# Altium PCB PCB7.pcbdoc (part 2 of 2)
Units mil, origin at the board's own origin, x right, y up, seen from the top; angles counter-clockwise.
Board outline 2240.69 x 1522.77 mil, 8 copper layers (Top Layer, Inner1, Inner2, Inner3, Inner4, Inner5, Inner6, Bottom Layer); 54 components, 78 nets, 968 pads, 282 vias.
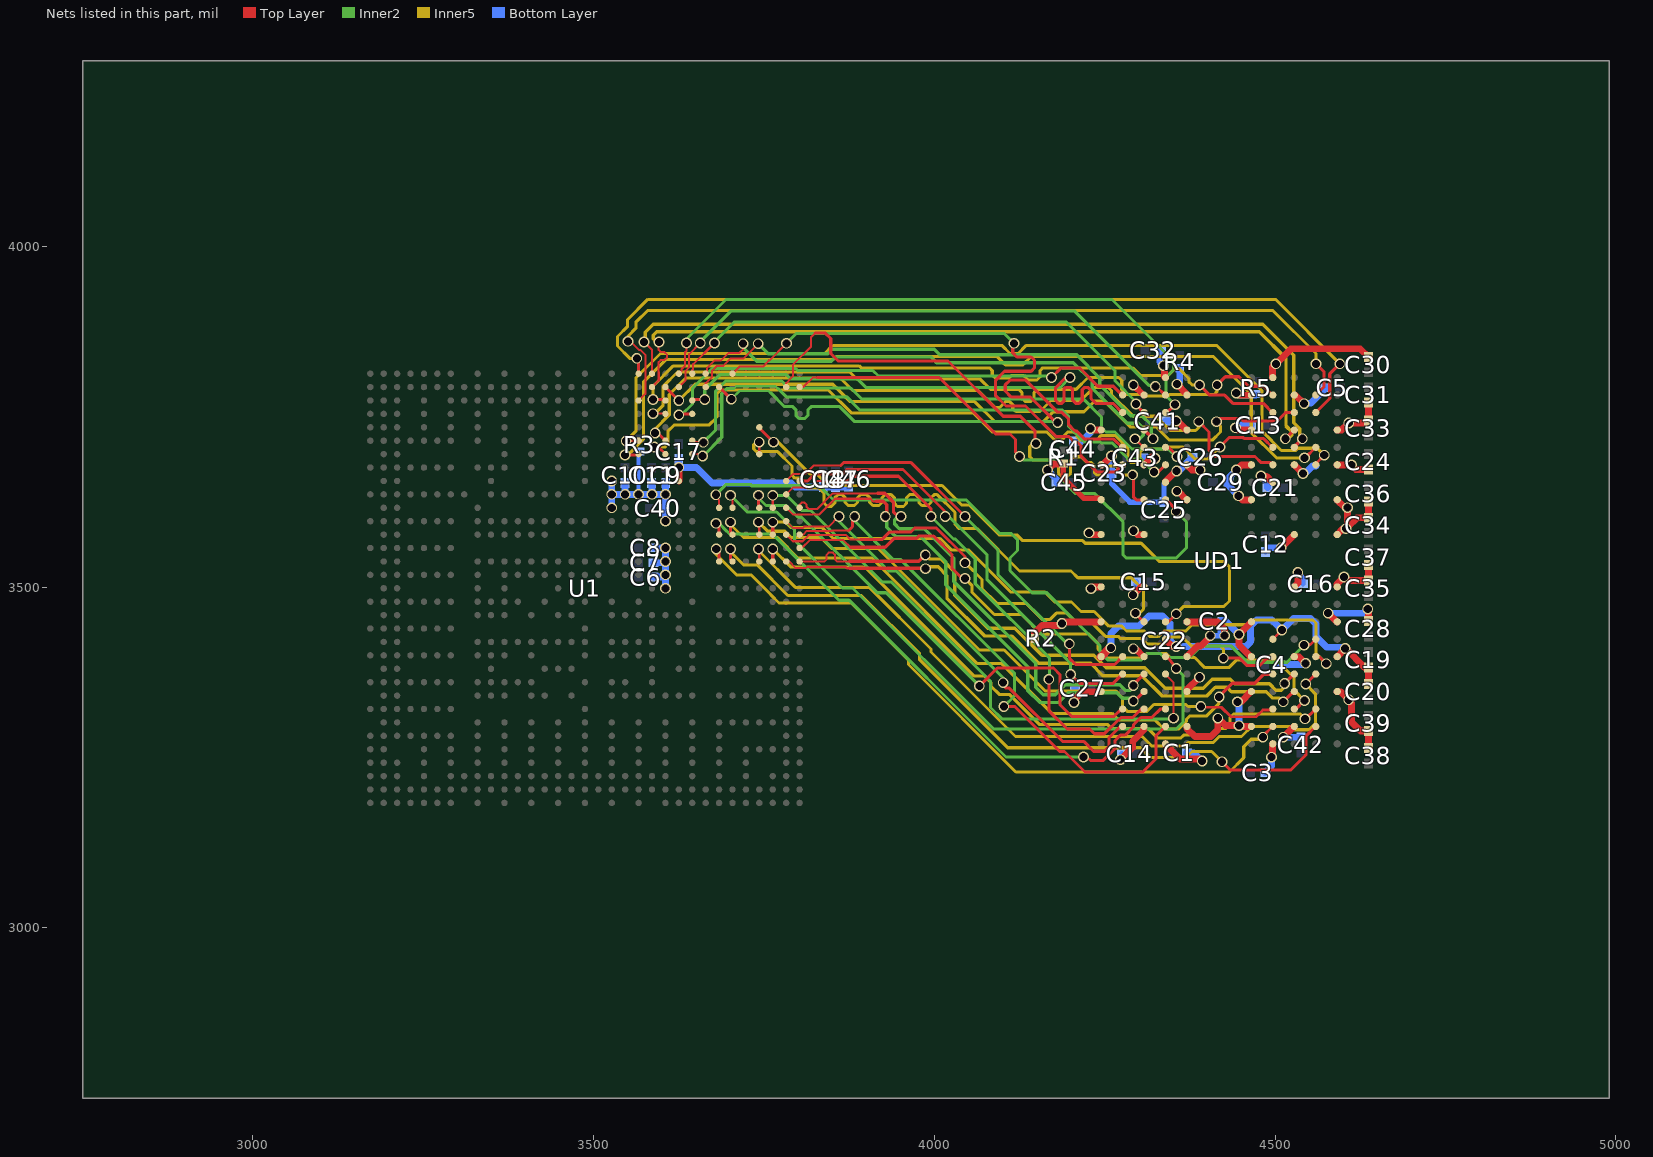
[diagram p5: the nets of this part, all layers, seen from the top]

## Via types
v1: diameter 15.75, hole 11.81, Top Layer to Bottom Layer, 282 vias

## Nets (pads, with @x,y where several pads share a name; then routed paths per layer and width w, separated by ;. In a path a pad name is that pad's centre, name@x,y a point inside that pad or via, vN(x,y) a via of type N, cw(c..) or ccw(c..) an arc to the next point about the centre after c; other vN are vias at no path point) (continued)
SCS0-A: U1.AN32 UD1.H4 | length 826.4
  Top Layer w3: U1.AN32@3802.23,3793.68 3807.9,3793.68 3821.99,3807.77 3827.87,3807.77
  Top Layer w4.5: 3827.87,3807.77 4007,3807.77 4090,3724.77 4111,3724.77 4119,3716.77 4119,3697.77 v1(4125,3691.77) ; UD1.H4@4338.78,3628.07 4340.7,3628.07 4355,3613.77 v1(4355,3610.77)
  Inner2 w4.5: v1(4125,3691.77) 4130,3686.77 4179.49,3686.77 4189.5,3676.76 4189.5,3654.76 4206.99,3637.27 4235.5,3637.27 4277,3595.77 4277,3547.27 4281.5,3542.77 4355,3542.77 4370,3557.77 4370,3595.77 v1(4355,3610.77)
SCS0-B: U1.AK29 UD1.R4 | length 932.3
  Top Layer w4.5: U1.AK29@3743.18,3734.62 3743.18,3733.59 v1(3764,3712.77) ; UD1.R4@4338.78,3448.93 4343.16,3448.93 v1(4355,3460.77)
  Inner5 w4.5: v1(3764,3712.77) 3771,3712.77 3818,3665.77 3828,3665.77 3844.5,3649.27 4011.43,3649.27 4039.93,3620.77 4051,3620.77 4095,3576.77 4121,3576.77 4129.5,3568.27 4217.54,3568.27 4221.43,3564.38 4303.39,3564.38 4330,3537.77 4425,3537.77 4433,3529.77 4433,3479.77 4425,3471.77 4366,3471.77 v1(4355,3460.77)
SCS1-A: U1.AM32 UD1.H3 | length 813.7
  Top Layer w3: U1.AM32@3782.55,3793.68 3782.56,3799.47 3792.38,3809.28 3792.38,3826.15 3819.31,3853.08 3819.31,3867.08 3825,3872.77
  Top Layer w4.5: 3825,3872.77 3840,3872.77 3848,3864.77 3848,3842.77 3859,3831.77 4020,3831.77 4101,3750.77 4126.02,3750.77 4148,3728.79 4148,3711.77 v1(4149,3710.77) ; v1(4291,3664.77) 4292,3663.77 4292,3632.57 4296.5,3628.07 UD1.H3@4307.28,3628.07
  Inner5 w4.5: v1(4149,3710.77) 4144.5,3710.77 4140,3706.27 4140,3691.27 4144.5,3686.77 4177.5,3686.77 4182,3682.27 4182,3667.27 4186.5,3662.77 4195.5,3662.77 4200,3667.27 4200,3686.83 4204.5,3691.33 4215.44,3691.33 4224,3682.77 4230.5,3682.77 4235,3678.27 4235,3667.77 4238,3664.77 4247.96,3664.77 4252.46,3669.27 4252.46,3673.27 4256.96,3677.77 4265.96,3677.77 4270.46,3673.27 4270.46,3669.27 4274.96,3664.77 v1(4291,3664.77)
SCS1-B: U1.AK27 UD1.R3 | length 888.4
  Top Layer w4: v1(3743,3712.77) 3743.18,3712.59 U1.AK27@3743.17,3695.18
  Top Layer w4.5: v1(4295,3461.77) 4295,3461.2 UD1.R3@4307.27,3448.93
  Inner5 w4.5: v1(3743,3712.77) 3738.62,3712.77 3734.99,3709.14 3734.99,3702.78 3739,3698.77 3770,3698.77 3791,3677.77 3791,3664.27 3795.25,3660.02 3803.75,3660.02 3808,3655.77 3808,3650.77 3813,3645.77 3830,3645.77 3838,3637.77 3838,3623.46 3842.81,3618.65 3849.18,3618.65 3854,3623.47 3854,3631.27 3858.5,3635.77 3864.66,3635.77 3869.16,3631.27 3869.16,3624.27 3873.66,3619.77 3882.66,3619.77 3887.16,3624.27 3887.16,3631.27 3891.66,3635.77 3900.66,3635.77 3905.16,3631.27 3905.16,3624.27 3909.66,3619.77 3918.66,3619.77 3923.16,3624.27 3923.16,3631.27 3927.66,3635.77 3936.66,3635.77 3941.16,3631.27 3941.16,3622.97 3945.67,3618.46 3954.65,3618.46 3959.16,3622.97 3959.16,3631.27 3963.66,3635.77 3972.66,3635.77 3977.16,3631.27 3977.16,3624.27 3981.66,3619.77 3990.66,3619.77 3995.16,3624.27 3995.16,3631.27 3999.66,3635.77 4004.16,3635.77 4030.25,3609.68 4030.25,3591.96 4036.45,3585.76 4062.86,3585.76 4124.85,3523.77 4200.51,3523.77 4210.51,3513.77 4289,3513.77 4307,3495.77 4307,3467.77 4301,3461.77 v1(4295,3461.77)
SDQ0: U1.AE28 UD1.E4 | length 860.7
  Top Layer w4.5: U1.AE28@3644.75,3714.94 3647.18,3712.51 v1(3660.95,3712.51) ; UD1.E4@4338.78,3704.84 4343.93,3704.84 4356,3692.77 v1(4356,3691.77)
  Inner2 w4.5: v1(3660.95,3712.51) 3679,3730.56 3679,3787.77 3693.44,3802.21 3776.56,3802.21 3786.5,3792.27 3877.16,3792.27 3893.16,3776.27 4218.5,3776.27 4245,3749.77 4245,3734.77 4252,3727.77 4265,3727.77 4290,3702.77 4343,3702.77 4354,3691.77 v1(4356,3691.77)
SDQ1: U1.AE27 UD1.F4 | length 840.3
  Top Layer w3: U1.AE27@3644.75,3695.25 3657.21,3695.25 v1(3659.96,3692.51)
  Top Layer w4.5: v1(4322.52,3668.82) 4323.05,3668.82 4324,3669.77 4329.3,3669.77 UD1.F4@4338.78,3679.25
  Inner2 w3: 3706,3791.77 3709,3794.77 3767,3794.77 3770,3791.77
  Inner2 w4.5: v1(3659.96,3692.51) 3660.74,3692.51 3688,3719.77 3688,3783.77 3696,3791.77 3706,3791.77 ; 3770,3791.77 3782.5,3779.27 3871.5,3779.27 3891,3759.77 4188,3759.77 4196.75,3751.02 4196.75,3736.01 4219.47,3713.29 4243.14,3713.29 4245.16,3711.27 4261.5,3711.27 4285,3687.77 4303.57,3687.77 v1(4322.52,3668.82)
SDQ2: U1.AG32 UD1.E2 | length 877.4
  Top Layer w4.5: U1.AG32@3684.12,3793.68 v1(3702,3775.77) ; v1(4181,3741.77) 4178,3741.77 4141,3778.77 4113,3778.77 4104,3787.77 4104,3796.77 4111,3803.77 4134,3803.77 4181,3756.77 4187,3756.77 4197,3746.77 4197,3738.36 4205.51,3729.85 4206.34,3729.85 4207.42,3728.77 4209,3728.77 4220.59,3717.18 4263.45,3717.18 UD1.E2@4275.79,3704.84
  Inner2 w3: v1(3702,3775.77) 3714,3787.77 3757,3787.77 3759,3785.77
  Inner2 w4.5: 3759,3785.77 3780,3764.77 3792.2,3764.77 3796.7,3760.27 3796.7,3752.27 3801.2,3747.77 3810.2,3747.77 3814.7,3752.27 3814.7,3760.27 3819.2,3764.77 3861,3764.77 3883,3742.77 4180,3742.77 v1(4181,3741.77)
SDQ3: U1.AH33 UD1.F2 | length 839.4
  Top Layer w3: U1.AH33@3703.81,3813.36 3714.22,3823.77 3749,3823.77 3752.5,3827.27 3752.5,3827.88 3756.89,3832.27 3757.5,3832.27 v1(3783,3857.77)
  Top Layer w4.5: v1(4117,3857.77) 4115,3855.77 4115,3843.77 4121,3837.77 4142,3837.77 4147,3832.77 4147,3821.77 4142,3816.77 4103,3816.77 4090,3803.77 4090,3780.77 4105,3765.77 4133.66,3765.77 4178.66,3720.77 4197.5,3720.77 4206,3712.27 4210.5,3712.27 4215,3707.77 4215,3692.77 4239.09,3668.68 4265.22,3668.68 UD1.F2@4275.79,3679.25
  Inner2 w4.5: v1(3783,3857.77) 3797.75,3872.52 4102.25,3872.52 v1(4117,3857.77)
SDQ4: U1.AE30 UD1.B2 | length 740.8
  Top Layer w4.5: v1(3625,3752.77) 3626.54,3754.31 U1.AE30@3644.75,3754.31 ; v1(4172,3807.52) 4186.25,3821.77 4213,3821.77 4240,3794.77 4262.63,3794.77 UD1.B2@4275.79,3781.61
  Inner2 w4.5: v1(3625,3752.77) 3629,3752.77 3645,3768.77 3645,3791.77 3674,3820.77 3797,3820.77 3800,3817.77 3910,3817.77 3918,3809.77 4169.75,3809.77 v1(4172,3807.52)
SDQ5: U1.AD32 UD1.B4 | length 831.9
  Top Layer w3: U1.AD32@3625.07,3793.68 3634.93,3803.54 3634.93,3817.43 3640.15,3822.65 3640.15,3841.9 v1(3656.48,3858.23)
  Top Layer w4.5: v1@4324.38,3794.39 4325,3793.77 4326.62,3793.77 UD1.B4@4338.78,3781.61
  Inner2 w4.5: v1(3656.48,3858.23) 3656.48,3860.23 3701.77,3905.52 4205.25,3905.52 4314.7,3796.07 4322.61,3796.07 v1(4324.29,3794.39)
SDQ6: U1.AE31 UD1.C2 | length 817.4
  Top Layer w4.5: U1.AE31@3644.75,3773.99 3646.24,3775.49 v1(3663.07,3775.49) ; v1(4199,3807.52) 4192.75,3807.52 4178,3792.77 4178,3773.77 4182,3769.77 4187,3769.77 4190,3772.77 4190,3790.12 4193,3793.12 4199.65,3793.12 4203,3789.77 4203,3774.27 4207.5,3769.77 4212.5,3769.77 4217,3774.27 4217,3789.77 4220,3792.77 4226,3792.77 4230,3788.77 4230,3776.52 4236.75,3769.77 4262.04,3769.77 UD1.C2@4275.79,3756.02
  Inner2 w4.5: v1(3663.07,3775.49) 3663.07,3789.84 3685,3811.77 3783,3811.77 3789,3805.77 3887,3805.77 3900,3792.77 4184.25,3792.77 v1(4199,3807.52)
SDQ7: U1.AD33 UD1.C4 | length 924.5
  Top Layer w3: U1.AD33@3625.07,3813.36 3628.93,3817.22 3628.93,3819.92 3634.15,3825.14 3634.15,3844.39 3636.38,3846.62 v1(3636.38,3858.33)
  Top Layer w4.5: UD1.C4@4338.78,3756.02 4341.25,3756.02 v1(4353,3767.77)
  Inner2 w4.5: v1(3636.38,3858.33) 3636.38,3864.15 3694.25,3922.02 4260.75,3922.02 4351,3831.77 4351,3818.77 4340,3807.77 4340,3780.77 v1(4353,3767.77)
SDQ8: U1.AC27 UD1.E9 | length 1109.3
  Top Layer w4.5: v1(3588.95,3705.51) 3595.12,3705.51 U1.AC27@3605.36,3695.18 ; v1(4419,3705.77) 4433,3719.77 4453,3719.77 4454.89,3717.88 4483.22,3717.88 UD1.E9@4496.26,3704.84
  Inner5 w4.5: v1(3588.95,3705.51) 3604.49,3705.51 3609,3710.02 3609,3728.77 3618,3737.77 3669,3737.77 3681,3749.77 3681,3783.77 3686.25,3789.02 3844.74,3789.02 3877.99,3755.77 4056.9,3755.77 4084.9,3727.77 4165,3727.77 4177,3715.77 4186.77,3715.77 4191.27,3720.27 4191.27,3723.27 4195.77,3727.77 4204.77,3727.77 4209.27,3723.27 4209.27,3720.27 4213.77,3715.77 4238,3715.77 4245,3722.77 4265,3722.77 4284,3703.77 4284,3687.27 4288.5,3682.77 4297.5,3682.77 4302,3687.27 4302,3698.27 4306.5,3702.77 4337,3702.77 4340,3705.77 4365,3705.77 4383,3687.77 4401,3687.77 v1(4419,3705.77)
SDQ9: U1.AC28 UD1.F9 | length 1107.7
  Top Layer w4.5: v1(3590.28,3726.13) 3594.19,3726.13 U1.AC28@3605.36,3714.86 ; v1(4388,3742.77) 4403,3727.77 4403,3700.77 4412,3691.77 4470.62,3691.77 4479.62,3682.77 4492.74,3682.77 UD1.F9@4496.26,3679.25
  Inner5 w4.5: v1(3590.28,3726.13) 3590.28,3732.05 3611,3752.77 3611,3782.77 3635,3806.77 3862,3806.77 3880,3788.77 4064,3788.77 4089.31,3763.46 4095.69,3763.46 4105,3772.77 4110,3772.77 4115,3767.77 4115,3762.27 4119.5,3757.77 4155,3757.77 4171.08,3773.85 4214.92,3773.85 4233.84,3792.77 4255.5,3792.77 4260,3788.27 4260,3782.77 4292,3750.77 4325,3750.77 4346,3729.77 4383.5,3729.77 4388,3734.27 v1(4388,3742.77)
SDQ10: U1.AC30 UD1.B9 | length 1059.2
  Top Layer w3: v1(3587.08,3754.49) 3605.2,3754.49 U1.AC30@3605.38,3754.31
  Top Layer w4.5: v1(4415,3796.77) 4427,3808.77 4447,3808.77 4461,3794.77 4483.1,3794.77 UD1.B9@4496.26,3781.61
  Inner5 w4.5: v1(3587.08,3754.49) 3589.72,3754.49 3602,3766.77 3602,3794.77 3623,3815.77 3876.01,3815.77 3886.51,3805.27 4067.5,3805.27 4082.42,3790.35 4123.9,3790.35 4128.4,3785.85 4128.4,3777.27 4132.9,3772.77 4141.9,3772.77 4146.4,3777.27 4146.4,3785.85 4150.9,3790.35 4208.08,3790.35 4225.5,3807.77 4270.5,3807.77 4275,3803.27 4275,3789.77 4282,3782.77 4306,3782.77 4308,3780.77 4343,3780.77 4345,3782.77 4410.5,3782.77 4415,3787.27 v1(4415,3796.77)
SDQ11: U1.AC31 UD1.C9 | length 1026.9
  Top Layer w4.5: v1(3587.07,3775.49) 3603.89,3775.49 U1.AC31@3605.38,3773.99 ; v1(4389,3796.77) 4404,3781.77 4426,3781.77 4438,3769.77 4482.51,3769.77 UD1.C9@4496.26,3756.02
  Inner5 w4.5: v1(3587.07,3775.49) 3587.07,3794.84 3617,3824.77 3889.63,3824.77 3892.63,3821.77 4081,3821.77 4085,3817.77 4085,3811.27 4089.5,3806.77 4110,3806.77 4114,3810.77 4131,3810.77 4137.92,3803.85 4150.5,3803.85 4155,3808.35 4155,3817.77 4159,3821.77 4291,3821.77 4302,3810.77 4343,3810.77 4352.81,3820.58 4359.19,3820.58 4373.5,3806.27 4373.5,3801.27 4378,3796.77 v1(4389,3796.77)
SDQ12: U1.AA33 UD1.C11 | length 1287.4
  Top Layer w4.5: v1(3563.34,3835.77) 3566.01,3833.1 U1.AA33@3566.01,3813.36 ; UD1.C11@4559.25,3756.02 4580.18,3776.95 4580.18,3812.95 v1(4595,3827.77)
  Inner5 w4.5: v1(3563.34,3835.77) 3553,3835.77 3535,3853.77 3535,3867.77 3550,3882.77 3550,3892.77 3579.5,3922.27 4500.5,3922.27 v1(4595,3827.77)
SDQ13: U1.AA31 UD1.B11 | length 1239.9
  Top Layer w3: v1(3550.53,3860.77) 3554.01,3860.77 3566.51,3848.27 3568.52,3848.27 3575.84,3840.95 3575.84,3783.82 U1.AA31@3566.01,3773.99
  Top Layer w4.5: UD1.B11@4559.25,3781.61 4572,3794.36 4572,3815.77 v1(4560,3827.77)
  Inner5 w4.5: v1(3550.53,3860.77) 3550.53,3868.29 3562,3879.76 3562,3888.77 3579,3905.77 4497,3905.77 4560,3842.77 v1(4560,3827.77)
SDQ14: U1.AA28 UD1.F11 | length 1280.3
  Top Layer w4: v1(3547.7,3714.49) 3548.15,3714.94 U1.AA28@3565.99,3714.86
  Top Layer w4.5: UD1.F11@4559.25,3679.25 4559.25,3680.76 v1(4572.14,3693.65)
  Inner5 w4.5: v1(3547.7,3714.49) 3562,3728.79 3562,3806.77 3598,3842.77 3839,3842.77 3851,3854.77 4099,3854.77 4111,3842.77 4123,3842.77 4135,3854.77 4414,3854.77 4481,3787.77 4481,3728.77 4509.19,3700.58 4530.81,3700.58 4534,3703.77 4561.91,3703.77 4572,3693.68 v1@4572.1,3693.68
SDQ15: U1.AA27 UD1.E11 | length 1253.4
  Top Layer w4.5: v1(3546,3693.77) 3564.53,3693.77 U1.AA27@3565.99,3695.18 ; v1(4543,3689.77) 4544.18,3689.77 UD1.E11@4559.25,3704.84
  Inner5 w4.5: v1(3546,3693.77) 3550,3693.77 3573,3716.77 3573,3800.77 3606,3833.77 3851,3833.77 3855.5,3838.27 4092.16,3838.27 4104.16,3826.27 4129.84,3826.27 4141.84,3838.27 4409.5,3838.27 4465,3782.77 4465,3726.77 4502,3689.77 v1(4543,3689.77)
SDQ16: U1.AM25 UD1.U2 | length 665.7
  Top Layer w3: U1.AM25@3782.55,3655.88 3792.38,3665.7 3810.14,3665.7 3822.71,3678.27 3862.31,3678.27
  Top Layer w4.5: 3862.31,3678.27 3866.81,3682.77 3966,3682.77 v1(4045,3603.77) ; v1(4198,3416.77) 4198,3395.77 4207.27,3386.5 4264.54,3386.5 UD1.U2@4275.79,3397.75
  Inner2 w4.5: v1(4045,3603.77) 4045,3603.11 4093.5,3554.61 4093.5,3518.27 4195,3416.77 v1(4198,3416.77)
SDQ17: U1.AN25 UD1.V2 | length 651.2
  Top Layer w4.5: U1.AN25@3802.23,3655.88 3814.11,3655.88 3824,3665.77 3864,3665.77 3871,3672.77 3954,3672.77 4015,3611.77 4015,3604.77 v1(4016,3603.77) ; v1(4200,3371.77) 4212.86,3358.91 4262.54,3358.91 UD1.V2@4275.79,3372.16
  Inner2 w4.5: v1(4016,3603.77) 4021,3603.77 4077,3547.77 4077,3511.43 4200,3388.43 v1(4200,3371.77)
SDQ18: U1.AH23 UD1.U4 | length 946.1
  Top Layer w3: v1(3700.96,3634.77) 3703.82,3631.91 U1.AH23@3703.82,3616.52
  Top Layer w4.5: UD1.U4@4338.78,3397.75 4342.67,3397.2 v1(4355,3380.77)
  Inner2 w4.5: v1(3700.96,3634.77) 3725.46,3610.27 3768.5,3610.27 3795,3583.77 3795,3568.77 3865,3498.77 3879.99,3498.77 4086.99,3291.77 4355,3291.77 4365,3301.77 4365,3370.77 v1(4355,3380.77)
SDQ19: U1.AK23 UD1.Y2 | length 741.8
  Top Layer w4.5: v1(3741.96,3634.77) 3741.96,3617.73 U1.AK23@3743.18,3616.51 ; v1(4066,3354.77) 4092.5,3381.27 4174.84,3381.27 4184.5,3371.61 4184.5,3327.27 4201.36,3310.41 4263.72,3310.41 4274.29,3320.98 UD1.Y2@4275.79,3320.98
  Inner2 w4.5: v1(3741.96,3634.77) 3741.96,3630.81 3753,3619.77 3783,3619.77 3800,3602.77 3805,3602.77 3916,3491.77 3929.35,3491.77 4066,3355.12 v1(4066,3354.77)
SDQ20: U1.AL23 UD1.V4 | length 834.6
  Top Layer w3: UD1.V4@4338.78,3372.16 4351,3359.94 v1(4351,3307.77)
  Top Layer w4: U1.AL23@3762.87,3616.52 v1(3762.87,3634.68)
  Inner2 w4.5: v1(3762.87,3634.68) 3783.09,3634.68 3805,3612.77 3818.34,3612.77 3923.83,3507.28 3937.18,3507.28 4082.5,3361.96 4082.5,3323.28 4099.01,3306.77 4350,3306.77 v1(4351,3307.77)
SDQ21: U1.AM22 UD1.AA2 | length 679.8
  Top Layer w3: U1.AM22@3782.55,3596.83 3792.38,3587.01 3807.24,3587.01 3808.9,3588.67 3844.9,3588.67 v1(3860,3603.77)
  Top Layer w4.5: v1(4101,3359.77) 4101,3356.27 4105.5,3351.77 4110,3351.77 4188,3273.77 4219,3273.77 4233.54,3259.23 4249.46,3259.23 4256,3265.77 4256,3278.76 4272.63,3295.39 UD1.AA2@4275.79,3295.39
  Inner2 w4.5: v1(3860,3603.77) 3860,3596.77 3932.98,3523.79 3944.01,3523.79 4101,3366.8 v1(4101,3359.77)
SDQ22: U1.AN21 UD1.AA4 | length 813
  Top Layer w3: U1.AN21@3802.22,3577.07 3807.36,3577.14 3812.89,3582.67 3849.9,3582.67 3850.33,3583.1 3874.33,3583.1
  Top Layer w4.5: 3874.33,3583.1 3880,3588.77 3880,3602.77 3881,3603.77 v1(3883,3603.77) ; v1(4102,3324.77) 4118,3324.77 4184,3258.77 4191,3258.77 4221,3228.77 4306,3228.77 4325,3247.77 4325,3281.61 UD1.AA4@4338.78,3295.39
  Inner2 w4.5: v1(3883,3603.77) 3883,3597.11 3939.81,3540.3 3950.84,3540.3 4117.5,3373.64 4117.5,3340.27 v1(4102,3324.77)
SDQ23: U1.AG21 UD1.Y4 | length 871.7
  Top Layer w4: v1(3679.59,3593.7) 3680.13,3593.7 3684.13,3589.7 3684.13,3586.92 ; U1.AG21@3684.11,3577.06 3684.13,3586.92 ; U1.AG21@3684.13,3577.15 3684.13,3586.92
  Top Layer w4.5: v1(4219,3250.77) 4224,3250.77 4229,3245.77 4248,3245.77 4265,3262.77 4265,3274.77 4273,3282.77 4280,3282.77 4292.08,3294.85 4292.08,3297.77 4303.08,3308.77 4319.08,3308.77 4331.29,3320.98 UD1.Y4@4338.78,3320.98
  Inner2 w4.5: v1(3679.59,3593.7) 3683.92,3593.7 3695.47,3582.15 3695.62,3582.15 3700,3577.77 3763,3577.77 3860,3480.77 3875,3480.77 4105,3250.77 v1(4219,3250.77)
SDQ24: U1.AG19 UD1.AA9 | length 1018.4
  Top Layer w4: v1(3679.96,3556.03) 3684.13,3551.86 U1.AG19@3684.13,3537.78
  Top Layer w4.5: v1(4482,3279.77) 4482,3281.13 UD1.AA9@4496.26,3295.39
  Inner5 w4.5: v1(3679.96,3556.03) 3679.96,3547.81 3710,3517.77 3731.5,3517.77 3760,3489.27 3760,3488.77 3772,3476.77 3878,3476.77 3962,3392.77 3962,3386.43 4119.66,3228.77 4433,3228.77 4454,3249.77 4454,3265.77 4465,3276.77 4479,3276.77 v1(4482,3279.77)
SDQ25: U1.AH19 UD1.AA11 | length 1069.6
  Top Layer w4.5: U1.AH19@3700.96,3540.54 U1.AH19@3703.8,3537.7 ; U1.AH19@3700.96,3540.62 v1(3700.96,3556.03) ; v1(4422,3243.77) 4434,3231.77 4523,3231.77 4545,3253.77 4545,3281.14 UD1.AA11@4559.25,3295.39
  Inner5 w4.5: v1(3700.96,3556.03) 3700.96,3551.81 3720,3532.77 3740,3532.77 3785,3487.77 3893,3487.77 3978.5,3402.27 3978.5,3393.27 4107.5,3264.27 4302.5,3264.27 4317,3249.77 4369,3249.77 4378,3258.77 4407,3258.77 v1(4422,3243.77)
SDQ26: U1.AK19 UD1.V11 | length 1061.4
  Top Layer w4: v1(3741.96,3556.03) 3743.19,3554.8 U1.AK19@3743.19,3537.78
  Top Layer w4.5: v1(4545,3357.77) 4545,3357.91 UD1.V11@4559.25,3372.16
  Inner5 w4.5: v1(3741.96,3556.03) 3741.96,3553.81 3796,3499.77 3904.35,3499.77 3995,3409.11 3995,3404.77 4119,3280.77 4305,3280.77 4319,3266.77 4367,3266.77 4372,3271.77 4409,3271.77 4418,3280.77 4450.63,3280.77 4465.63,3295.77 4521,3295.77 4526,3290.77 4550,3290.77 4559,3299.77 4559,3343.77 v1(4545,3357.77)
SDQ27: U1.AL19 UD1.Y11 | length 961.4
  Top Layer w4.5: U1.AL19@3762.87,3537.78 v1(3762.87,3555.94) ; v1(4544,3306.77) 4545.04,3306.77 UD1.Y11@4559.25,3320.98
  Inner5 w4.5: v1(3762.87,3555.94) 3789.04,3529.77 3897.68,3529.77 4057.68,3369.77 4073,3369.77 4083,3359.77 4083,3354.77 4095,3342.77 4110,3342.77 4154.5,3298.27 4254.5,3298.27 4260,3292.77 4313,3292.77 4327,3278.77 4362,3278.77 4366,3282.77 4407,3282.77 4417,3292.77 4428,3292.77 4434,3298.77 4434,3308.77 4439,3313.77 4537,3313.77 v1(4544,3306.77)
SDQ28: U1.AM21 UD1.U9 | length 857.2
  Top Layer w3: U1.AM21@3782.55,3577.14 3792.37,3567.32 3806.56,3567.32 3815.55,3576.31 3870.46,3576.31 3877,3569.77 3891.67,3569.77
  Top Layer w4.5: 3891.67,3569.77 3923,3569.77 3934,3580.77 3965,3580.77 3971,3586.77 4003,3586.77 4044.9,3544.87 v1(4044.9,3535.67) ; v1(4424,3395.77) 4448,3395.77 4459,3384.77 4477,3384.77 4489.98,3397.75 UD1.U9@4496.26,3397.75
  Inner5 w4.5: v1(4044.9,3535.67) 4045.44,3535.67 4070,3511.11 4070,3497.77 4091.5,3476.27 4134.84,3476.27 4158.34,3452.77 4170,3452.77 4179,3461.77 4194.32,3461.77 4208.32,3447.77 4231,3447.77 4251,3427.77 4270,3427.77 4273,3424.77 4304,3424.77 4312,3416.77 4336,3416.77 4346,3426.77 4364,3426.77 4377,3413.77 4419.5,3413.77 4424,3409.27 v1(4424,3395.77)
SDQ29: U1.AL21 UD1.U11 | length 982.6
  Top Layer w4.5: U1.AL21@3762.87,3577.15 v1(3762.87,3595.31) ; UD1.U11@4559.25,3397.75 4565.1,3397.75 v1(4575.08,3387.77)
  Inner5 w4.5: v1(3762.87,3595.31) 3781.46,3595.31 3789.5,3587.27 3835.5,3587.27 3851.5,3571.27 4008.5,3571.27 4025.01,3554.76 4050.01,3554.76 4112,3492.77 4162,3492.77 4176.5,3478.27 4201.16,3478.27 4215.16,3464.27 4234.5,3464.27 4256,3442.77 4275,3442.77 4282,3435.77 4308,3435.77 4316.43,3427.34 4328.49,3427.34 4336.92,3435.77 4369,3435.77 4378,3444.77 4462,3444.77 4469,3451.77 4555.5,3451.77 4560,3447.27 4560,3402.85 v1(4575.08,3387.77)
SDQ30: U1.AK21 UD1.Y9 | length 911.9
  Top Layer w4: v1(3741.96,3595.4) 3743.19,3594.17 U1.AK21@3743.19,3577.15 ; v1(4391,3324.77) 4392,3323.77 4421,3323.77 4435,3309.77 4472.01,3309.77 4481.97,3319.73 4495.01,3319.73 UD1.Y9@4496.26,3320.98
  Inner5 w4.5: v1(3741.96,3595.4) 3755.3,3582.06 3780.71,3582.06 3790,3572.77 3833,3572.77 3849,3556.77 3917.36,3556.77 4066.36,3407.77 4102.39,3407.77 4162.39,3347.77 4266,3347.77 4276,3337.77 4276,3324.77 4283,3317.77 4312,3317.77 4322,3327.77 4369,3327.77 4372,3324.77 v1(4391,3324.77)
SDQ31: U1.AH21 UD1.V9 | length 979.8
  Top Layer w4.5: U1.AH21@3700.96,3579.99 v1(3700.96,3595.4) ; v1(4418,3338.77) 4418,3339.77 4437.21,3358.98 4470.2,3358.98 4483.38,3372.16 UD1.V9@4496.26,3372.16
  Inner5 w4.5: v1(3700.96,3595.4) 3700.96,3591.81 3720,3572.77 3770,3572.77 3800,3542.77 3908.02,3542.77 4063.02,3387.77 4099.05,3387.77 4172.05,3314.77 4261,3314.77 4271,3304.77 4324.01,3304.77 4337.01,3291.77 4359,3291.77 4370,3302.77 4370,3306.27 4374.5,3310.77 4399,3310.77 4418,3329.77 v1(4418,3338.77)
SDQM0: U1.AE33 UD1.C3 | length 768.7
  Top Layer w3: U1.AE33@3644.75,3813.36 3644.63,3813.49 3644.63,3818.64 3646.15,3820.16 3646.15,3827.07 v1(3677.31,3858.23)
  Top Layer w4.5: v1(4296,3768.77) 4296,3767.3 UD1.C3@4307.28,3756.02
  Inner2 w4.5: v1(3677.31,3858.23) 3677.48,3858.4 3677.48,3860.23 3706.27,3889.02 4193.75,3889.02 4265,3817.77 4265,3802.77 4296,3771.77 v1(4296,3768.77)
SDQM1: U1.AC32 UD1.C10 | length 1036.8
  Top Layer w4.5: U1.AC32@3605.38,3793.68 3605.38,3793.39 v1(3625,3773.77) ; v1(4414,3742.77) 4419,3747.77 4449,3747.77 4453,3743.77 4503,3743.77 4515.25,3756.02 UD1.C10@4527.76,3756.02
  Inner5 w4.5: v1(3625,3773.77) 3649,3797.77 3851,3797.77 3876.5,3772.27 4059.5,3772.27 4089,3742.77 4160,3742.77 4174.58,3757.35 4219.58,3757.35 4235,3772.77 4250,3772.77 4288,3734.77 4326,3734.77 4345,3715.77 4408,3715.77 4420,3727.77 4420,3736.77 v1(4414,3742.77)
SDQM2: U1.AM24 UD1.Y3 | length 782
  Top Layer w3: U1.AM24@3782.55,3636.2 3792.41,3646.06 3818.29,3646.06 3828,3655.77 3867,3655.77
  Top Layer w4.5: 3867,3655.77 3873,3655.77 3880,3662.77 3947.44,3662.77 3995,3615.21 v1(3995,3603.77) ; v1(4168,3364.77) 4168,3318.77 4195,3291.77 4228,3291.77 4234.95,3284.82 4249.44,3284.82 4269.39,3304.77 4270.22,3304.77 4274.22,3308.77 4291,3308.77 4303.21,3320.98 UD1.Y3@4307.28,3320.98
  Inner2 w4.5: v1(3995,3603.77) 4028,3570.77 4030.66,3570.77 4060,3541.43 4060,3505.09 4167,3398.09 4167,3397.72 4169,3395.72 4169,3365.77 v1(4168,3364.77)
SDQM3: U1.AN20 UD1.Y10 | length 924.8
  Top Layer w3: U1.AN20@3802.23,3557.46 3805.7,3557.46 3817.3,3569.06 3847.99,3569.06 3848.08,3569.15 3858.43,3569.15 3858.53,3569.06 3866.44,3569.06 3877,3558.5
  Top Layer w4.5: 3877,3558.5 3927.73,3558.5 3941,3571.77 3974,3571.77 3977,3574.77 3999,3574.77 4026,3547.77 4026,3527.77 4041,3512.77 v1(4045,3512.77) ; UD1.Y10@4527.76,3320.98 4530.21,3320.98 v1(4543,3333.77)
  Inner5 w4.5: v1(4045,3512.77) 4055,3502.77 4055,3492.77 4088,3459.77 4128,3459.77 4156.75,3431.02 4226.75,3431.02 4240,3417.77 4240,3409.77 4254,3395.77 4305,3395.77 4312,3402.77 4340,3402.77 4346,3396.77 4382,3396.77 4397,3381.77 4432,3381.77 4443,3392.77 4502,3392.77 4528,3366.77 4528,3348.77 v1(4543,3333.77)
SDQS0N: U1.AF33 UD1.E3 | length 777.5
  Top Layer w3: U1.AF33@3664.44,3813.36 3666.26,3815.18 3666.26,3821.35 3677.68,3832.77 3687.02,3832.77 3698.02,3843.77 3714,3843.77 3719.48,3849.25 v1(3719.48,3857.23)
  Top Layer w3.8: v1(4294.48,3717.64) UD1.E3@4307.28,3704.84
  Inner2 w5: v1(3719.48,3857.23) 3719.48,3851.12 3739.33,3831.27 3848.51,3831.27 3855.01,3837.77 3994.92,3837.77 4003.17,3829.52 4203.98,3829.52 4231.5,3802 4231.5,3791.99 4283.22,3740.27 4299.44,3740.27 4306.5,3733.24 4306.5,3722.69 4301.51,3717.66 v1(4294.48,3717.64)
SDQS0P: U1.AF32 UD1.D3 | length 789.5
  Top Layer w3: U1.AF32@3664.44,3793.68 3664.44,3799.21 3674,3808.77 3674,3817.77 3681,3824.77 3690.34,3824.77 3701.34,3835.77 3720.02,3835.77 v1(3741.48,3857.23)
  Top Layer w5: UD1.D3@4307.28,3730.43 4308.34,3730.43 v1(4321,3717.77)
  Inner2 w5: v1(3741.48,3857.23) 3755.94,3842.77 3843.74,3842.77 3850.24,3849.27 3999.69,3849.27 4007.94,3841.02 4208.75,3841.02 4243,3806.77 4243,3796.76 4287.99,3751.77 4304.19,3751.77 4318,3738.02 4318.03,3720.72 v1(4321,3717.77)
SDQS1N: U1.AB33 UD1.E10 | length 1187.6
  Top Layer w3: v1(3574,3859.77) 3585.7,3848.07 U1.AB33@3585.7,3813.36
  Top Layer w5: UD1.E10@4527.76,3704.84 4527.76,3705.53 v1(4540,3717.77)
  Inner5 w5: v1(3574,3859.77) 3576,3861.77 3576,3874.28 3587.74,3886.02 4481.75,3886.02 4527.5,3840.27 4527.5,3741.27 4536.02,3732.75 4536.02,3721.87 4540,3717.89 v1(4540,3717.77)
SDQS1P: U1.AB32 UD1.D10 | length 1194.6
  Top Layer w3: U1.AB32@3585.7,3793.68 3595.56,3803.54 3595.5,3830.08 3598.5,3833.08 3603.87,3833.08 3607.74,3836.95 3607.74,3841.2 3603.86,3845.08 3598.5,3845.08 3595.5,3848.08 3595.5,3854.27 3596,3854.77 v1(3596,3859.77)
  Top Layer w5: v1(4515,3717.77) UD1.D10@4527.66,3730.43
  Inner5 w5: v1(3596,3859.77) 3592.5,3859.77 3587.5,3864.77 3587.5,3869.51 3592.51,3874.52 4476.98,3874.52 4516,3835.5 4516,3736.5 4524.52,3727.98 4524.52,3722.79 4519.5,3717.77 v1(4515,3717.77)
SDQS2N: U1.AN23 UD1.V3 | length 741.1
  Top Layer w3: U1.AN23@3802.23,3616.51 3802.23,3621.02 3805.24,3624.03 3809.48,3624.03 3812.49,3621.02 3812.49,3617.65 3815.49,3614.65 3827.88,3614.65 3850.94,3637.71 3916.63,3637.7
  Top Layer w5: 3916.63,3637.7 3927.22,3637.7 3940,3624.92 3940,3610.77 3947,3603.77 v1(3951,3603.77) ; v1(4292,3355.77) 4292,3356.88 UD1.V3@4307.28,3372.16
  Inner2 w5: v1(3951,3603.77) 3947,3603.77 3941.5,3598.27 3941.5,3592.78 3948.51,3585.77 3985.06,3585.77 4028.5,3542.33 4028.5,3508.28 4148.75,3388.03 4148.75,3353.01 4159.49,3342.27 4177.51,3342.27 4192.01,3356.77 4272.27,3356.77 4280.77,3348.27 4287,3348.27 4292,3353.27 v1(4292,3355.77)
SDQS2P: U1.AM23 UD1.W3 | length 740.4
  Top Layer w3: U1.AM23@3782.55,3616.51 3792.37,3606.69 3831.2,3606.65 3854.26,3629.71 3906.06,3629.71 3910.08,3625.69 3914.33,3625.69
  Top Layer w5: 3914.33,3625.69 3914.41,3625.77 3925,3625.77 3930,3620.77 3930,3605.77 v1(3928,3603.77) ; v1(4292,3332.77) 4292.39,3333.16 4293.87,3333.16 UD1.W3@4307.28,3346.57
  Inner2 w5: v1(3928,3603.77) 3930,3601.77 3930,3588.01 3943.74,3574.27 3980.29,3574.27 4017,3537.56 4017,3503.51 4137.25,3383.26 4137.25,3348.24 4154.72,3330.77 4182.28,3330.77 4196.78,3345.27 4267.5,3345.27 4276,3336.77 4288,3336.77 v1(4292,3332.77)
SDQS3N: U1.AN19 UD1.V10 | length 873.1
  Top Layer w3: U1.AN19@3802.23,3537.77 3838.97,3537.77 3841.97,3540.77 3841.97,3547.5 3844.98,3550.51 3850.97,3550.51 3853.97,3547.51 3853.97,3540.77 3856.97,3537.77 3875.71,3537.75
  Top Layer w5: 3875.71,3537.75 3977.22,3537.75 v1(3986.75,3547.28) ; v1(4514,3358.77) 4527.39,3372.16 UD1.V10@4527.76,3372.16
  Inner5 w5: v1(3986.75,3547.28) 3987.27,3547.28 3993.28,3541.27 4010.49,3541.27 4030,3521.76 4030,3488.34 4078.57,3439.77 4118,3439.77 4158,3399.77 4234,3399.77 4252,3381.77 4308.99,3381.77 4338.99,3351.77 4394.73,3351.77 4407.73,3364.77 4434.26,3364.77 4440.76,3358.27 4491.77,3358.27 4501.27,3348.77 4509,3348.77 4514,3353.77 v1(4514,3358.77)
SDQS3P: U1.AM19 UD1.W10 | length 870.7
  Top Layer w3: U1.AM19@3782.55,3537.77 3786.99,3537.77 3796.81,3527.95 3811.56,3527.95 3813.38,3529.77 3869.56,3529.75 3871.56,3527.75 3875.71,3527.75
  Top Layer w5: 3875.71,3527.75 3986.34,3527.75 v1(3987,3527.09) ; v1(4512,3331.77) 4526.8,3346.57 UD1.W10@4527.76,3346.57
  Inner5 w5: v1(3987,3527.09) 3989.68,3529.77 4005.72,3529.77 4018.5,3516.99 4018.5,3483.57 4073.8,3428.27 4113.23,3428.27 4153.23,3388.27 4229.23,3388.27 4247.23,3370.27 4304.22,3370.27 4334.22,3340.27 4399.5,3340.27 4412.5,3353.27 4429.49,3353.27 4435.99,3346.77 4487,3346.77 4496.5,3337.27 4506.5,3337.27 v1(4512,3331.77)
SRST: U1.AG23 UD1.T11 | length 1099.2
  Top Layer w3: v1(3679.31,3635.56) 3680.09,3634.79 3680.09,3631.43 3684.13,3627.39 U1.AG23@3684.12,3616.51
  Top Layer w4: v1(4542.52,3414.77) 4543,3415.25 4543.48,3415.25 4543.99,3415.76 4551.67,3415.76 UD1.T11@4559.25,3423.34
  Inner2 w4.5: v1(3679.31,3635.56) 3694.52,3650.77 3729.99,3650.77 3731.99,3648.77 3831,3648.77 3852,3627.77 4047,3627.77 4096,3578.77 4112.98,3578.77 4122,3569.75 4122,3553.77 4111,3542.77 4111,3524.11 4143.34,3491.77 4165,3491.77 4243,3413.77 4243,3404.77 4255,3392.77 4303,3392.77 4313,3402.77 4331,3402.77 4337,3396.77 4375,3396.77 4392,3413.77 4435,3413.77 4459,3389.77 4517.52,3389.77 v1(4542.52,3414.77)
VCC-DRAM: C1.1 C2.1 C3.2 C4.2 C5.2 C6.2 C7.2 C8.2 C9.2 C10.2 C11.2 C12.2 C13.2 C14.2 C15.2 C16.2 C27.1 C28.1 C29.2 C30.2 C31.2 C32.1 C33.2 C34.2 C35.2 C36.2 C37.2 C38.2 C39.2 C40.2 C41.2 C42.2 C43.2 C44.2 C45.2 R1.2 R2.2 R3.2 R4.2 R5.2 U1.AA24 U1.AB24 U1.AC17 U1.AC18 U1.AC19 U1.AC20 U1.AC22 U1.AC24 U1.W23 U1.W24 U1.W25 U1.Y24 UD1.A4 UD1.A9 UD1.AA3 UD1.AA5 UD1.AA8 UD1.AA10 UD1.AB4 UD1.AB9 UD1.B3 UD1.B5 UD1.B8 UD1.B10 UD1.D1 UD1.D5 UD1.D8 UD1.D12 UD1.F3 UD1.F5 UD1.F8 UD1.F10 UD1.H1 UD1.H5 UD1.H8 UD1.H12 UD1.K1 UD1.K3 UD1.K10 UD1.K12 UD1.N1 UD1.N3 UD1.N10 UD1.N12 UD1.R1 UD1.R5 UD1.R8 UD1.R12 UD1.U3 UD1.U5 UD1.U8 UD1.U10 UD1.W1 UD1.W5 UD1.W8 UD1.W12 | length 2984.3
  Top Layer w4.5: R2.2@4149.05,3429.82 4149.49,3429.38 R2.2@4149.49,3424.77
  Top Layer w8: R1.2@4189,3680.93 4189,3660.77 4219,3630.77 4241.59,3630.77 UD1.H1@4244.29,3628.07
  Top Layer w10: R2.2@4147.49,3424.77 4147,3425.26 4147,3432.77 4157.84,3443.61 4183.84,3443.61 v1(4187,3446.77) 4189.17,3448.94 UD1.R1@4244.29,3448.93 ; v1(4166,3671.77) 4175.16,3680.93 R1.2@4189,3680.93 ; v1(4205,3330.77) 4205,3334.47 4217.1,3346.57 UD1.W1@4244.29,3346.57 ; v1@4227.08,3579.77 4229.96,3576.89 UD1.K1@4244.29,3576.89 ; v1(4229,3732.77) 4231.34,3730.43 UD1.D1@4244.29,3730.43 ; v1(4230,3497.77) 4232.34,3500.11 UD1.N1@4244.29,3500.11 ; v1(4273,3246.77) 4291,3264.77 4291,3273.77 4307.28,3290.05 UD1.AA3@4307.28,3295.39 ; v1(4291.76,3488.77) 4303.1,3500.11 UD1.N3@4307.28,3500.11 ; v1(4292,3409.77) 4295.26,3409.77 UD1.U3@4307.28,3397.75 ; v1(4292,3796.77) 4292.12,3796.77 UD1.B3@4307.28,3781.61 ; v1(4292.08,3582.77) 4297.96,3576.89 UD1.K3@4307.28,3576.89 ; UD1.F3@4307.28,3679.25 4318.8,3690.77 4324,3690.77 v1@4324,3688.8 ; v1(4336.31,3825.02) 4337,3824.33 4337,3820.77 4337.78,3819.99 4337.78,3808.2 UD1.A4@4338.78,3807.2 ; UD1.AB4@4338.78,3269.8 4360.81,3247.77 4390,3247.77 v1(4393,3244.77) ; v1(4355,3743.77) 4356.94,3743.77 UD1.D5@4370.28,3730.43 ; v1(4355.84,3640.91) 4356,3640.91 4356,3640.77 4357.58,3640.77 UD1.H5@4370.28,3628.07 ; v1(4356,3797.77) 4370.28,3783.49 UD1.B5@4370.28,3781.61 ; UD1.AA5@4370.28,3295.39 4370.28,3292.8 4382.31,3280.77 4406,3280.77 4416,3290.77 v1(4416,3307.77) 4427,3296.77 v1(4447,3296.77) 4448.38,3295.39 UD1.AA8@4464.76,3295.39 ; UD1.W5@4370.28,3346.57 4370.28,3349.05 v1(4389,3367.77) ; UD1.U5@4370.28,3397.75 4386.3,3413.77 4391,3413.77 4405,3427.77 v1(4405,3428.77) ; UD1.R5@4370.28,3448.93 4416,3448.93 4426,3438.93 v1(4426,3428.77) ; UD1.F5@4370.28,3679.25 4377.76,3671.77 v1(4390,3671.77) ; v1(4442,3733.77) 4445.34,3730.43 UD1.D8@4464.76,3730.43 ; v1(4443,3784.77) 4446.16,3781.61 UD1.B8@4464.76,3781.61 ; v1(4443.07,3671.8) 4450.52,3679.25 UD1.F8@4464.76,3679.25 ; v1(4445,3331.77) 4449.96,3331.77 UD1.W8@4464.76,3346.57 ; v1(4446.35,3633.94) 4452.22,3628.07 UD1.H8@4464.76,3628.07 ; UD1.U8@4464.76,3397.75 4447.08,3415.43 v1(4447.08,3430.53) 4447.08,3430.77 4464.76,3448.45 UD1.R8@4464.76,3448.93 ; v1(4494.64,3250.55) 4496.26,3252.17 UD1.AB9@4496.26,3269.8 ; UD1.A9@4496.26,3807.2 4496.26,3822.95 v1(4501.08,3827.77) 4523.08,3849.77 4625,3849.77 C30.2@4637,3837.77 ; v1(4509,3557.77) 4527.76,3576.53 UD1.K10@4527.76,3576.89 ; v1(4512,3279.77) 4512.14,3279.77 UD1.AA10@4527.76,3295.39 ; UD1.U10@4527.76,3397.75 4535.43,3397.75 v1(4544.91,3388.27) ; UD1.N10@4527.76,3500.11 4533.45,3505.8 v1(4533.45,3521.33) ; UD1.F10@4527.76,3679.25 4528.52,3679.25 v1(4541,3666.77) ; UD1.B10@4527.76,3781.61 4530.24,3781.61 4542.54,3769.31 v1(4542.66,3769.31) ; v1(4577.95,3461.73) UD1.R12@4590.75,3448.93 ; UD1.W12@4590.75,3346.57 4596.2,3346.57 v1(4608,3334.77) 4612,3330.77 4612,3302.39 4625.62,3288.77 C39.2@4637,3288.77 C38.2@4637,3263.77 ; UD1.N12@4590.75,3500.11 4590.75,3504.52 v1(4601,3514.77) 4606,3509.77 C35.2@4637,3509.77 C37.2@4637,3532.77 ; UD1.K12@4590.75,3576.89 4599.63,3585.77 v1(4604,3585.77) v1@4606.31,3588.08 ; UD1.H12@4590.75,3628.07 4602.21,3616.61 v1(4606.31,3616.61) ; UD1.D12@4590.75,3730.43 4597.74,3730.43 v1(4608.08,3740.77) 4633,3740.77 C33.2@4637,3744.77 C31.2@4637,3770.77 ; v1@4606.9,3617.2 v1(4606.31,3616.61) ; v1(4636,3467.77) 4637,3466.77 C28.1@4637,3450.27 ; C36.2@4637,3625.77 C34.2@4637,3601.77 4620,3601.77 v1@4606.31,3588.08 ; v1@4606.31,3588.08 v1(4606.31,3616.61)
  Bottom Layer w6: v1(3566,3636.13) 3566,3697.26 R3.2@3568,3699.26
  Bottom Layer w8: v1(4273,3246.77) 4275.13,3248.9 C14.2@4275.13,3255.54 ; v1(4291.76,3488.77) 4296,3493.01 C15.2@4296,3507.77 ; v1(4405,3428.77) v1(4426,3428.77) ; v1(4533.45,3521.33) 4541,3513.78 C16.2@4541,3504.77
  Bottom Layer w10: v1(3526.63,3616.44) v1(3526.63,3636.13) ; v1(3526.62,3655.8) v1(3526.63,3636.13) ; C10.2@3546,3652.77 3546,3636.44 v1(3546.31,3636.13) ; C11.2@3585,3652.77 3585.69,3652.08 v1(3585.69,3636.13) ; C6.2@3588,3514.77 3602.12,3514.77 v1(3605.36,3518.02) ; C7.2@3588,3535.77 3603.45,3535.77 v1(3605.37,3537.7) ; C8.2@3588,3557.77 3604.98,3557.77 v1(3605.36,3557.39) v1(3605.37,3537.7) ; C40.2@3605,3615.77 C40.2@3605.37,3615.4 ; v1(3605.37,3498.32) v1(3605.36,3518.02) ; v1(3605.37,3596.75) C40.2@3605.37,3615.4 ; C9.2@3606,3652.77 3605.37,3652.14 v1(3605.37,3636.13) ; v1(4166,3671.77) 4180.16,3657.61 C45.2@4180.16,3652.77 ; v1(4205,3330.77) 4206.5,3332.27 C27.1@4206.5,3351.77 ; C44.2@4205,3712.61 4214.84,3712.61 4229,3726.77 v1(4229,3732.77) ; C43.2@4306,3689.77 4323.1,3689.77 v1(4324.07,3688.8) ; C32.1@4330.66,3847.68 4330.66,3830.67 v1(4336.31,3825.02) ; C41.2@4339,3743.77 v1(4355,3743.77) ; v1(4356,3797.77) 4360,3801.77 R4.2@4360,3820.93 ; C1.1@4369.84,3256.77 4381,3256.77 v1(4393,3244.77) ; v1(4426,3428.77) 4420.8,3433.97 4420.8,3451.06 4426.55,3451.06 v1(4447.08,3430.53) ; v1(4442,3733.77) 4446,3737.77 C13.2@4465.16,3737.77 ; v1(4443,3784.77) 4446.16,3781.61 R5.2@4471.71,3781.61 ; v1(4443.07,3671.8) 4429.84,3658.57 4429.84,3650.45 v1(4446.35,3633.94) ; v1(4445,3331.77) 4447,3329.77 v1(4447,3296.77) ; C3.2@4484.84,3227.77 4494.64,3237.57 v1(4494.64,3250.55) ; C12.2@4486,3552.93 4490.84,3557.77 v1(4509,3557.77) ; C4.2@4504.8,3386.43 4543.07,3386.43 v1(4544.91,3388.27) ; v1(4512,3279.77) C42.2@4538,3279.77 ; v1(4541,3666.77) 4544,3666.77 4554.84,3677.61 4560,3677.61 ; v1(4542.66,3769.31) 4543.12,3769.77 4552.12,3769.77 C5.2@4575.42,3793.07 ; v1(4577.95,3461.73) 4629.96,3461.73 v1(4636,3467.77) ; v1(3526.63,3636.13) v1(3546.31,3636.13) ; v1(3546.31,3636.13) v1(3566,3636.13) v1(3585.69,3636.13) ; v1(3585.69,3636.13) v1(3605.37,3636.13) ; v1(3605.36,3518.02) v1(3605.37,3537.7) ; C40.2@3605.37,3615.4 v1(3605.37,3636.13)
  other v1: 4227,3579.77
VDD18-DRAM: C17.1 C18.2 C46.1 C47.2 U1.AD25 | length 294.4
  Top Layer w10: U1.AD25@3625.05,3655.8 v1@3625.05,3675.72
  Bottom Layer w10: C17.1@3625,3687.77 v1(3625,3675.77) 3650.7,3675.77 3673.7,3652.77 3790,3652.77 3795.84,3646.93 C18.2@3836,3646.93 ; C18.2@3837,3647.93 C18.2@3836,3646.93 ; C46.1@3874,3647.27 3873.66,3646.93 C18.2@3836,3646.93
VDD18-LPDDR: C19.1 C20.2 C21.2 C22.2 C23.2 C24.2 C25.2 C26.2 UD1.F1 UD1.F12 UD1.G4 UD1.G9 UD1.T4 UD1.T9 UD1.U1 UD1.U12 | length 980.1
  Top Layer w4: UD1.T9@4496.26,3423.34 v1(4509.92,3437)
  Top Layer w10: UD1.F1@4244.29,3679.25 4246.48,3679.25 v1(4260,3692.77) ; UD1.T4@4338.78,3423.34 4349.35,3412.77 v1(4355,3412.77) ; UD1.G4@4338.78,3653.66 4338.78,3654.55 4354.73,3670.5 v1(4355.62,3670.5) ; v1(4479.4,3663.11) 4479.66,3663.11 4480,3662.77 4487.15,3662.77 UD1.G9@4496.26,3653.66 ; UD1.U12@4590.75,3397.75 v1(4602.91,3409.9) 4603.87,3409.9 4631.5,3382.27 C19.1@4637,3382.27 C20.2@4637,3357.77 ; UD1.F12@4590.75,3679.25 v1(4612,3679.25) 4618.48,3672.77 C24.2@4637,3672.77
  Top Layer w12: UD1.U1@4244.29,3397.75 4257.31,3410.77 4258.75,3410.77 v1(4259,3411.02)
  Bottom Layer w8: C23.2@4260,3666.77 4260,3651.77 4287,3624.77 C25.2@4337,3624.77 4337,3651.88 v1(4355.62,3670.5)
  Bottom Layer w10: v1(4259,3411.02) 4259,3431.77 4270,3442.77 4300,3442.77 4315,3457.77 4335,3457.77 4345.78,3446.99 C22.2@4345.78,3429.55 4345.78,3421.99 v1(4355,3412.77) 4457,3412.77 4464,3419.77 4464,3442.77 4473,3451.77 4495.15,3451.77 v1(4509.92,3437) 4510.23,3437 4527,3453.77 4552,3453.77 4560,3445.77 4560,3427.77 4576,3411.77 4601.04,3411.77 v1(4602.91,3409.9) ; C23.2@4260,3666.77 v1(4260,3692.77) ; v1(4355.62,3670.5) 4358.73,3670.5 C26.2@4379,3690.77 ; v1(4479.4,3663.11) 4489,3653.51 C21.2@4489,3645.77 ; v1(4612,3679.25) v1@4613.52,3679.25
pads on no net: U1.A2 U1.A3 U1.A4 U1.A5 U1.A6 U1.A8 U1.A10 U1.A12 U1.A14 U1.A16 U1.A18 U1.A20 U1.A22 U1.A24 U1.A26 U1.A28 U1.A29 U1.A30 U1.A31 U1.A32 U1.A33 U1.AA1 U1.AA2 U1.AA3 U1.AA4 U1.AA5 U1.AA6 U1.AA7 U1.AA9 U1.AA12 U1.AA13 U1.AA19 U1.AB2 U1.AB3 U1.AB9 U1.AB13 U1.AC2 U1.AC3 U1.AC4 U1.AC5 U1.AC6 U1.AC7 U1.AC9 U1.AC15 U1.AD1 U1.AD2 U1.AD15 U1.AE1 U1.AE2 U1.AE3 U1.AE4 U1.AE5 U1.AE6 U1.AE7 U1.AE11 U1.AE13 U1.AE16 U1.AF1 U1.AF2 U1.AG1 U1.AG2 U1.AG4 U1.AG5 U1.AG9 U1.AG13 U1.AG15 U1.AG17 U1.AH1 U1.AH2 U1.AH11 U1.AH13 U1.AH15 U1.AH17 U1.AJ1 U1.AJ2 U1.AJ3 U1.AJ4 U1.AJ5 U1.AJ7 U1.AJ9 U1.AJ11 U1.AJ15 U1.AJ17 U1.AK1 U1.AK2 U1.AK7 U1.AK9 U1.AK13 U1.AK15 U1.AK17 U1.AK33 U1.AL1 U1.AL2 U1.AL5 U1.AL7 U1.AL11 U1.AL15 U1.AL16 U1.AL17 U1.AL27 U1.AL32 U1.AL33 U1.AM1 U1.AM2 U1.AM3 U1.AM4 U1.AM6 U1.AM7 U1.AM8 U1.AM9 U1.AM10 U1.AM11 U1.AM12 U1.AM13 U1.AM14 U1.AM15 U1.AM16 U1.AM17 U1.AM18 U1.AM33 U1.AN2 U1.AN3 U1.AN4 U1.AN5 U1.AN6 U1.AN7 U1.AN8 U1.AN9 U1.AN13 U1.AN15 U1.AN17 U1.AN26 U1.B1 U1.B2 U1.B3 U1.B4 U1.B5 U1.B6 U1.B7 U1.B8 U1.B9 U1.B10 U1.B11 U1.B12 U1.B13 U1.B14 U1.B15 U1.B16 U1.B17 U1.B18 U1.B19 U1.B20 U1.B21 U1.B22 U1.B23 U1.B24 U1.B25 U1.B26 U1.B27 U1.B28 U1.B29 U1.B30 U1.B31 U1.B32 U1.B33 U1.C1 U1.C2 U1.C3 U1.C4 U1.C7 U1.C9 U1.C11 U1.C13 U1.C15 U1.C16 U1.C17 U1.C19 U1.C21 U1.C22 U1.C23 U1.C24 U1.C25 U1.C26 U1.C27 U1.C28 U1.C29 U1.C30 U1.C31 U1.C32 U1.C33 U1.D1 U1.D2 U1.D8 U1.D10 U1.D12 U1.D14 U1.D16 U1.D18 U1.D20 U1.D22 U1.D24 U1.D26 U1.D28 U1.D32 U1.D33 U1.E1 U1.E2 U1.E4 U1.E5 U1.E6 U1.E8 U1.E10 U1.E12 U1.E14 U1.E16 U1.E18 U1.E20 U1.E22 U1.E24 U1.E26 U1.E28 U1.E29 U1.E30 U1.E31 U1.E32 U1.E33 U1.F1 U1.F2 U1.F14 U1.F16 U1.F18 U1.F20 U1.F22 U1.F24 U1.F26 U1.F28 U1.F32 U1.F33 U1.G1 U1.G2 U1.G4 U1.G5 U1.G6 U1.G12 U1.G16 U1.G20 U1.G22 U1.G24 U1.G26 U1.G28 U1.G30 U1.G31 U1.G32 U1.G33 U1.H2 U1.H3 U1.H24 U1.H31 U1.H32 U1.J1 U1.J2 U1.J4 U1.J5 U1.J7 U1.J15 U1.J16 U1.J17 U1.J18 U1.J19 U1.J21 U1.J22 U1.J23 U1.J26 U1.J29 U1.J30 U1.J32 U1.J33 U1.K2 U1.K3 U1.K13 U1.K15 U1.K16 U1.K19 U1.K21 U1.K22 U1.K24 U1.K25 U1.K31 U1.K32 U1.L1 U1.L2 U1.L4 U1.L5 U1.L7 U1.L9 U1.L15 U1.L16 U1.L17 U1.L18 U1.L19 U1.L21 U1.L22 U1.L24 U1.L26 U1.L28 U1.L29 U1.L31 U1.L32 U1.M2 U1.M3 U1.M10 U1.M16 U1.M18 U1.M19 U1.M21 U1.M22 U1.M31 U1.M32 U1.N1 U1.N2 U1.N4 U1.N5 U1.N7 U1.N9 U1.N13 U1.N21 U1.N24 U1.N28 U1.N29 U1.N31 U1.N32 U1.N33 U1.P2 U1.P3 U1.P9 U1.P13 U1.P18 U1.P21 U1.P22 U1.P31 U1.P32 U1.R1 U1.R2 U1.R4 U1.R5 U1.R6 U1.R15 U1.R17 U1.R18 U1.R22 U1.R26 U1.R28 U1.R29 U1.R30 U1.R31 U1.R32 U1.R33 U1.T2 U1.T3 U1.T9 U1.T11 U1.T13 U1.T19 U1.T21 U1.T22 U1.T31 U1.T32 U1.U1 U1.U2 U1.U3 U1.U4 U1.U5 U1.U6 U1.U8 U1.U10 U1.U12 U1.U13 U1.U18 U1.U19 U1.U21 U1.U22 U1.U26 U1.U28 U1.U29 U1.U30 U1.U31 U1.U32 U1.U33 U1.V2 U1.V3 U1.V31 U1.V32 U1.W1 U1.W2 U1.W3 U1.W4 U1.W5 U1.W6 U1.W7 U1.W9 U1.W10 U1.W19 U1.W21 U1.W28 U1.W29 U1.W31 U1.W32 U1.W33 U1.Y2 U1.Y3 U1.Y9 U1.Y10 U1.Y12 U1.Y13 U1.Y19 U1.Y21 U1.Y31 U1.Y32 UD1.A1 UD1.A2 UD1.A11 UD1.A12 UD1.AA1 UD1.AA12 UD1.AB1 UD1.AB2 UD1.AB11 UD1.AB12 UD1.B1 UD1.B12 UD1.G11 UD1.K5 UD1.K8 UD1.N5 UD1.N8

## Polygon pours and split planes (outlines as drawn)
GND on Top Layer (solid, remove dead copper, pour order 10): 3000,3001.77 4737,3001.77 4737,4022.77 3000,4022.77
GND on Bottom Layer (solid, remove dead copper, pour order 16): 3003.69,3000 4740.69,3000 4740.69,4021 3003.69,4021
GND on Inner1 (solid, remove dead copper): 3523,3603.77 3579,3603.77 3591,3591.77 3591,3495.77 3623,3463.77 3866,3463.77 4120,3209.77 4629,3209.77 4649,3229.77 4649,3838.77 4533,3954.77 3577,3954.77 3512,3889.77 3512,3614.77
GND on Inner6 (solid, remove dead copper): 3523.48,3603.27 3579.48,3603.27 3591.48,3591.27 3591.48,3495.27 3623.48,3463.27 3866.48,3463.27 4120.48,3209.27 4629.48,3209.27 4649.48,3229.27 4649.48,3838.27 4533.48,3954.27 3577.48,3954.27 3512.48,3889.27 3512.48,3614.27
GND on Inner1 (solid, remove dead copper): 3523.06,3602.71 3579.06,3602.71 3591.06,3590.71 3591.06,3494.71 3623.06,3462.71 3866.06,3462.71 4120.06,3208.71 4629.06,3208.71 4649.06,3228.71 4649.06,3837.71 4533.06,3953.71 3577.06,3953.71 3512.06,3888.71 3512.06,3613.71
GND on Inner3 (solid, remove dead copper): 3522.5,3603.27 3578.5,3603.27 3590.5,3591.27 3590.5,3495.27 3622.5,3463.27 3865.5,3463.27 4119.5,3209.27 4628.5,3209.27 4648.5,3229.27 4648.5,3838.27 4532.5,3954.27 3576.5,3954.27 3511.5,3889.27 3511.5,3614.27
VCC-DRAM on Inner4 (solid, remove dead copper): 3523.18,3604.27 3579.18,3604.27 3591.18,3592.27 3591.18,3496.27 3623.18,3464.27 3866.18,3464.27 4120.18,3210.27 4629.18,3210.27 4649.18,3230.27 4649.18,3839.27 4533.18,3955.27 3577.18,3955.27 3512.18,3890.27 3512.18,3615.27
VDD18-LPDDR on Bottom Layer (solid, remove dead copper, pour order 14): 4204,3858.77 4147.53,3802.3 4147.53,3271.24 4201,3217.77 4593.51,3217.77 4645.26,3269.52 4645.26,3813.46 4599.95,3858.77

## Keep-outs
Top Layer:
  region: 3542,3862.77 3542,3672.37 3549.35,3665.02 3653.75,3665.02 3668,3650.77 3668,3536.77 3677,3527.77 3782,3527.77 3786,3523.77 3831,3523.77 3858,3496.77 4098,3496.77 4122.51,3472.26 4122.51,3422.42 4101.3,3401.21 4088.44,3401.21 4052,3364.77 4052,3327.76 4081.99,3297.77 4125,3297.77 4203,3219.77 4599,3219.77 4615,3235.77 4615,3841.77 4614,3842.77 4170,3842.77 4132,3880.77 4105.11,3880.77 4092.16,3867.82 4092.16,3832.21 4077.72,3817.77 4052.75,3817.77 4025.75,3844.77 3870.53,3844.77 3860.53,3854.77 3860.53,3873.25 3844.76,3889.02 3568.25,3889.02
Inner2:
  region: 3599.55,3865.32 3671,3936.77 4278.83,3936.77 4377.33,3838.27 4614.56,3838.27 4616.82,3836.01 4616.82,3249.03 4595.56,3227.77 4095,3227.77 3861,3461.77 3829,3461.77 3747,3543.77 3659,3543.77 3599.55,3603.22
Inner5:
  region: 3526,3695.81 3546.31,3675.5 3748.57,3675.5 3764.3,3659.77 3764.3,3618.51 3756.06,3610.27 3696.16,3610.27 3667,3581.11 3667,3547.77 3710.28,3504.49 3723.47,3504.49 3762.19,3465.77 3860,3465.77 4112,3213.77 4606.88,3213.77 4645.63,3252.52 4645.63,3356.4 4648,3358.77 4648,3795.77 4508,3935.77 3582.55,3935.77 3526,3879.22
Board Outline Layer:
  lines w10: 3027,3039.77 4717,3039.77 4717,3991.77 3027,3991.77 3027,3039.77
